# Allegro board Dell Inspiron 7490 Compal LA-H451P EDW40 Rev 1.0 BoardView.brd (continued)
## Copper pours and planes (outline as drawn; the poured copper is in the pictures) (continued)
+TBT_VBUS_L_PD on TOP (solid shape): 27.89,33.92 28.14,33.92 28.3,34.08 30.26,34.08 30.85,33.49 31.36,33.49 31.58,33.26 31.58,30.18 31.48,30.07 30.35,30.07 30.35,30.26 28.62,30.26 28.62,30.24 28.01,30.24 28.01,30.07 27.34,30.07 26.93,29.67 26.93,27.11 26.74,26.92 24.76,26.92 24.65,27.03 24.65,28.46 24.65,28.46 24.65,33.79 24.94,34.08 27.73,34.08
+TBT_VBUS_L_PD on BOTTOM (solid shape): 27.09,34 27.09,33.07 26.99,32.96 25.64,32.96 25.63,32.98 24.45,32.98 24.39,33.03 24.39,33.62 24.43,33.66 25.45,33.66 25.91,34.12 26.98,34.12
+TBT_VBUS_L_PD on BOTTOM (solid shape): 26.53,28.8 26.53,27.36 26.3,27.13 24.69,27.13 24.66,27.14 24.57,27.14 24.47,27.23 24.47,27.27 24.4,27.34 24.4,29.6 24.42,29.62 25.7,29.62
+TBT_VBUS_L_PD on IN1 (solid shape): 27.11,34.04 27.11,32.13 26.33,31.35 26.33,31.11 26.32,31.04 26.33,30.97 26.33,30.78 26.35,30.76 26.35,28.12 26.2,27.97 24.7,27.97 24.56,28.1 24.56,28.89 24.57,28.9 24.57,31.65 24.58,31.66 24.58,33.19 25.05,33.67 25.54,33.67 25.99,34.12 27.03,34.12
+TBTA_VBUS on TOP (solid shape): 33.29,34.99 33.29,34.45 33.38,34.36 33.61,34.36 33.67,34.3 33.67,33.47 34.44,32.69 34.44,30.36 34.2,30.11 32.19,30.11 32.04,30.26 32.04,34.43 32.04,34.43 32.04,34.99 32.12,35.07 33.22,35.07
+TBTA_VBUS on TOP (solid shape): outline of 249 points within 7.16,56.62 15.3,71.87
+TBTA_VBUS on BOTTOM (solid shape): 11.05,65.05 11.05,64.75 10.83,64.53 10.02,64.53 9.98,64.56 9.94,64.6 9.88,64.64 9.83,64.68 8.86,64.68 8.63,64.46 7.3,64.46 7.26,64.5 7.26,64.72 7.32,64.78 8.2,64.78 8.52,64.7 8.73,64.96 8.73,64.97 8.82,65.06 10.49,65.06 10.59,65.16 10.94,65.16
+TBTA_VBUS on BOTTOM (solid shape): 11.33,67.55 11.33,67.25 11.27,67.2 11.14,67.2 11.02,67.15 9.75,67.15 9.69,67.22 8.41,67.22 8.15,66.96 7.34,66.96 7.26,67.04 7.26,67.27 7.29,67.29 8.06,67.29 8.29,67.52 8.32,67.5 8.48,67.46 8.63,67.53 9.72,67.53 9.76,67.58 9.78,67.58 9.89,67.61 9.99,67.67 11.21,67.67
+TBTA_VBUS on IN2 (solid shape): outline of 430 points within 7.17,62.2 13.12,70.46
+TBTA_VBUS on IN3 (solid shape): outline of 367 points within 7.17,64.26 12.08,70.55
+TBTA_VBUS on VCC: 32.77,29.43 32.55,29.65 24.06,29.65 24.06,29.67 23.93,29.8 23.93,29.86 23.91,29.88 23.91,44.23 22.86,45.28 17.52,45.28 17.16,45.64 17.16,61.06 16.08,62.14 7.91,62.14 7.83,62.23 7.83,70.31 22.73,70.31 23.03,70.02 23.03,70.02 23.08,69.96 23.08,51.1 24.73,49.45 30.58,49.45 31.62,48.41 31.62,47.14 31.62,47.14 31.62,46.93 31.62,46.93 31.62,35 32.26,34.36 33.67,34.36 33.68,34.35 34.88,34.35 35.72,33.51 35.72,32.04 33.11,29.43
+TP_VDD on TOP (solid shape): 121.31,10.52 121.31,9.94 121.28,9.94 121.28,9.41 121.15,9.28 121,9.28 121,8.47 121.02,8.47 121.02,6.98 121,6.98 121,6.17 121.02,6.17 121.02,6.03 121.07,5.98 121.07,5.31 121.01,5.25 119.05,5.25 118.77,5.53 115.9,5.53 115.76,5.66 115.76,6.53 115.83,6.6 116.73,6.6 116.82,6.57 116.91,6.56 117.09,6.56 117.39,6.67 117.56,6.94 117.56,6.96 117.71,7.1 118.4,7.1 118.56,6.94 119.3,6.94 119.63,6.61 120.14,6.61 120.33,6.81 120.33,7.34 120.16,7.5 120.16,8.3 119.53,8.3 119.53,8.24 115.97,8.24 115.86,8.35 115.86,9.14 115.92,9.19 116.47,9.19 116.55,9.11 117.39,9.11 117.65,8.85 119.62,8.85 119.72,8.95 119.94,8.95 120.12,9.13 120.15,9.16 120.18,9.19 120.33,9.34 120.33,10.41 120.46,10.54 121.28,10.54
+TP_VDD on BOTTOM (solid shape): 125.86,12.79 125.86,10.94 125.64,10.73 123.86,10.73 123.78,10.81 123.78,12.9 123.81,12.93 125.72,12.93
+TP_VDD_N on TOP (solid shape): 117.4,9.87 117.47,9.87 117.68,9.65 118.35,9.65 118.39,9.62 118.39,9.2 118.33,9.14 117.62,9.14 117.49,9.27 116.57,9.27 116.49,9.35 116.49,9.84 116.58,9.93 117.34,9.93
+TP_VDD_P on TOP (solid shape): 121.28,11.61 121.28,10.94 121.21,10.88 120.47,10.88 120.05,10.46 119.45,10.46 119.39,10.52 119.39,11.08 119.47,11.16 119.95,11.16 120.47,11.69 121.2,11.69
+TS_VDD on TOP (solid shape): 41.45,54.87 41.81,54.87 41.88,54.8 41.88,54.09 41.7,53.91 41.31,53.91 41.31,51.73 40.3,51.73 39.67,52.36 39.67,52.76 40.78,53.87 40.78,54.87 41.44,54.87
+V_DDR_REF_CA on BOTTOM (solid shape): 176.38,60.6 176.38,59.55 176.37,59.55 176.37,58.68 176.28,58.59 176.27,58.59 176.13,58.51 176.05,58.37 176.05,58.36 176.02,58.33 175.48,58.33 175.47,58.38 175.42,58.51 175.3,58.6 175.27,58.61 175.27,59.44 175.21,59.5 175.21,60.68 175.25,60.72 176.27,60.72
+V_DDR_REFA_R on BOTTOM (solid shape): 179.28,61.55 179.28,59.88 177.94,58.54 177.94,58.51 177.93,58.5 177.86,58.31 177.94,58.12 177.94,57.97 177.9,57.95 177.71,57.73 177.83,57.46 177.87,57.38 177.85,57.3 177.76,57.22 177.3,57.22 177.2,57.32 177.2,57.59 177.38,57.77 177.38,58.13 177.33,58.18 177.33,58.38 177.38,58.43 177.38,58.61 177.74,58.97 177.74,60.16 178.24,60.65 178.24,61.55 178.3,61.61 179.22,61.61
+V_DDR_REFB_R on BOTTOM (solid shape): 177.57,61.59 177.57,60.09 177.25,59.77 177.25,58.49 177.2,58.43 177.2,58.13 177.25,58.08 177.25,57.83 177.13,57.7 176.77,57.7 176.64,57.83 176.64,61.08 176.54,61.18 176.54,61.58 176.59,61.64 177.53,61.64
+VCHGR on TOP: 94.75,12.94 95.63,12.94 95.81,12.76 95.81,11.18 95.69,11.06 91.99,11.06 91.67,11.37 91.67,13.25 92.22,13.8 93.9,13.8 94.75,12.95
+VDISPLAY_VCC on TOP (solid shape): 16.1,48.48 16.25,48.48 16.74,47.98 16.74,46.75 16.62,46.63 13.9,46.63 13.49,47.04 12.57,47.04 12.46,47.16 12.46,48.41 13.21,49.16 15.42,49.16
+VDISPLAY_VCC on IN2 (solid shape): outline of 570 points within 13.16,36.24 30.16,49.26
+VREFCA on BOTTOM (solid shape): 179.72,78.6 179.72,78.04 179.39,77.71 178.78,77.71 178.7,77.79 178.7,78.74 179.58,78.74
+VREFCA on BOTTOM (solid shape): 187.77,78.42 187.77,77.83 187.79,77.82 187.79,77.18 187.71,77.1 186.29,77.1 186.21,77.17 186.21,78.36 186.48,78.63 187.57,78.63
+VREFCA on IN1 (solid shape): 162.91,78.86 163.08,78.8 163.25,78.86 164.66,78.86 164.83,78.8 165.01,78.86 167.83,78.86 168.55,78.13 171.38,78.13 172.11,78.86 187.78,78.86 188,78.64 188,77.19 187.83,77.02 187.3,77.02 186.07,78.25 184.6,78.25 183.95,77.6 175.71,77.6 174.97,76.86 173,76.86 172.3,77.56 167.48,77.56 167.16,77.89 166.78,77.89 166.71,77.89 166.65,77.89 146.04,77.89 146.04,77.88 145.56,77.4 142.06,77.4 141.79,77.66 141.79,78.2 142.35,78.76 155.14,78.76 155.24,78.86
+VREFCA on IN3 (solid shape): 143.52,78.53 143.52,78.05 143.51,78.04 143.51,76.7 143.41,76.59 142.66,76.59 142.55,76.71 142.55,78.08 142.55,78.64 142.64,78.72 143.33,78.72
+VREFDQ_A on BOTTOM (solid shape): 183.04,63.93 183.04,63.53 182.85,63.34 182.3,63.34 182.23,63.28 182.16,63.28 182.16,63.2 182.13,63.18 182.13,61.4 184.7,58.83 184.7,55.15 184.72,55.13 184.72,54.07 184.61,53.96 183.9,53.96 183.71,54.15 183.71,55.03 184.11,55.44 184.11,58.43 181.59,60.95 181.59,60.95 181.41,61.14 181.41,61.57 181.19,61.79 180.6,61.79 180.57,61.76 178.28,61.76 178.24,61.8 178.24,62.18 178.36,62.3 180.25,62.3 180.46,62.51 180.46,63.23 180.6,63.36 181.47,63.36 182.16,64.06 182.91,64.06
+VREFDQ_B on BOTTOM (solid shape): 151.22,64.33 151.83,64.33 151.89,64.27 151.89,63.36 151.83,63.3 150.6,63.3 150.37,63.54 150.37,64.52 150.53,64.68 150.87,64.68
+VREFDQ_B on BOTTOM (solid shape): 162.08,64.36 162.08,62.61 161.95,62.47 161.1,62.47 161.02,62.55 161.02,63.72 160.95,63.79 160.95,64.53 161.07,64.66 161.79,64.66
+VREFDQ_B on BOTTOM (solid shape): 180.27,63.27 180.27,62.79 180.22,62.74 179.68,62.74 179.65,62.77 177.5,62.77 177,62.27 177,62.21 176.99,62.19 176.99,61.76 176.54,61.76 176.52,61.79 176.52,63.18 176.79,63.45 180.09,63.45
ADJ_UM2 on TOP (solid shape): 29.89,36.37 29.89,36.17 29.73,36.01 28.74,36.01 28.55,35.82 28.55,35.49 28.44,35.38 27.57,35.38 27.49,35.46 27.49,36.13 27.53,36.17 27.92,36.17 28.05,36.3 28.05,36.4 28.07,36.42 29.84,36.42
ADP_CHG on BOTTOM (solid shape): 195.03,21.26 195.03,21.25 193.62,19.85 193.62,17.53 193.45,17.36 192.96,17.36 192.96,17.39 191.99,17.39 191.99,18 192.11,18.12 192.49,18.12 192.62,18.25 192.65,18.25 192.65,18.28 193.13,18.76 193.13,19.85 193.25,19.97 193.25,20.15 194.53,21.43 194.53,21.94 194.78,22.19 195.03,22.19
ALL_SYS_PWRGD on TOP (solid shape): 64.69,18.04 64.69,17.17 64.62,17.1 63,17.1 62.78,17.32 62.78,17.81 63.06,18.09 63.57,18.09 63.83,18.03 64.08,18.12 64.6,18.12
B+ on TOP (solid shape): 74.24,13.22 74.24,11.61 73.95,11.32 72.75,11.32 72.65,11.42 70.53,11.42 70.3,11.65 70.3,13.17 70.49,13.36 74.11,13.36
B+ on TOP (solid shape): 68.92,61.56 68.92,60.24 68.69,60.01 67.68,60.01 67.25,60.44 61.33,60.44 60.54,59.64 58.09,59.64 57.91,59.82 57.91,60.2 59.73,62.01 68.47,62.01
B+ on TOP (solid shape): 140.23,16.45 140.23,16.03 141.76,14.51 141.76,13.17 141.69,13.11 138.52,13.11 138.39,13.24 138.39,13.55 138.58,13.74 138.58,14.12 138.39,14.31 137.31,14.31 135.92,15.71 135.92,16.66 136.04,16.79 139.89,16.79
B+ on TOP (solid shape): 44.52,72.95 47.41,72.95 48.18,73.72 49.07,73.72 49.18,73.62 49.18,70.12 48.95,69.89 45.22,69.89 44.98,69.65 44.98,68 45.1,67.88 45.1,65.24 45.05,65.18 44.62,65.18 44.48,65.32 44.48,66.35 44.16,66.66 44.16,66.67 44.11,66.73 44.04,66.78 44.04,66.79 43.73,67.1 43.73,67.74 43.04,68.43 43.04,69.78 43.15,69.89 43.15,72.45 42.21,73.38 41.32,73.38 41.26,73.44 41.26,74.12 41.34,74.2 41.35,74.2 41.44,74.29 43.19,74.29
B+ on TOP (solid shape): 200.82,59.2 200.82,59.09 200.76,59.09 200.76,58.25 200.82,58.25 200.82,57.48 200.72,57.38 200.09,57.38 200.05,57.35 199.91,57.35 199.76,57.2 199.76,56.11 199.98,55.89 200.01,55.84 200.19,55.66 201.29,55.66 201.38,55.57 201.38,54.45 201.05,54.11 200.88,54.11 200.57,53.81 199.13,53.81 199.01,53.94 199.01,54.36 198.98,54.38 198.98,57.75 199.01,57.76 199.23,58.07 199.01,58.38 198.98,58.4 198.98,58.49 199.1,58.61 199.73,58.61 199.91,58.79 199.91,59.2 199.94,59.24 200.78,59.24
B+ on BOTTOM (solid shape): 188.38,7.56 188.38,6.49 188.09,6.21 186.75,6.21 186.47,6.48 185.89,6.48 185.62,6.21 185.62,5.7 185.52,5.6 180.8,5.6 180.8,5.6 180.51,5.6 180.43,5.68 180.43,7.33 180.81,7.71 188.23,7.71
B+ on BOTTOM (solid shape): 9.9,22.36 9.9,16.9 9.36,16.37 9.36,13.98 9.16,13.78 8.15,13.78 8.15,13.79 8.09,13.79 7.98,13.9 7.98,17.13 8.35,17.5 8.35,20.83 8.07,21.11 8.06,21.11 7.98,21.2 7.98,22.46 8.15,22.63 9.63,22.63
B+ on BOTTOM (solid shape): 137.4,19.26 138,19.26 138,19.26 138.15,19.1 138.15,18.69 138.22,18.62 138.22,17.1 138.54,16.77 138.55,16.77 138.61,16.71 138.68,16.71 138.68,16.66 139.75,16.66 139.75,16.71 139.85,16.71 139.85,16.66 140.04,16.66 140.04,16.66 140.04,16.23 139.93,16.12 135.51,16.12 135.11,16.52 135.11,18.39 135.03,18.47 134.56,18.47 134.51,18.53 134.51,19.15 134.62,19.26 137.4,19.26
B+ on BOTTOM (solid shape): 141.67,14.34 141.67,13.84 141.69,13.82 141.69,12.39 141.87,12.21 145.1,12.21 145.28,12.03 145.28,7.73 144.43,6.88 141.53,6.88 139.86,8.55 137.67,8.55 137.46,8.77 137.46,9.89 136.71,10.64 136.71,13.83 137.68,13.83 137.68,13.78 137.69,13.73 137.7,13.68 137.73,13.63 137.76,13.59 137.8,13.55 137.84,13.52 137.88,13.5 137.93,13.48 137.98,13.48 138.04,13.48 138.09,13.48 138.14,13.5 138.18,13.52 138.23,13.55 138.26,13.59 138.29,13.63 138.32,13.68 138.33,13.73 138.34,13.78 138.34,13.83 138.33,13.88 138.32,13.93 138.29,13.98 138.26,14.02 138.23,14.06 138.18,14.09 138.14,14.11 138.09,14.13 138.04,14.14 137.98,14.14 137.93,14.13 137.88,14.11 137.84,14.09 137.8,14.06 137.76,14.02 137.73,13.98 137.7,13.93 137.69,13.88 137.68,13.83 136.71,13.83 136.71,14.07 137.06,14.42 138.75,14.42 141.58,14.42
B+ on BOTTOM (solid shape): 207.55,31.53 207.55,30.79 207.96,30.38 208.14,29.7 208.14,29.12 208.11,29.1 206.39,29.1 206.29,29.2 206.29,29.95 206.22,30.02 205.46,30.02 205.37,29.94 205.35,29.94 205.25,29.83 205.25,29.82 205.21,29.77 205.21,27.26 205.45,27.02 205.45,23.79 205.45,23.79 205.45,23.33 204.81,22.7 204.81,18.12 204.62,17.93 204.01,17.93 203.67,17.59 203.67,17.29 203.37,16.98 202.41,16.98 202.4,17 200.73,17 200.62,17.11 200.62,17.97 200.62,19.01 200.78,19.17 202.47,19.17 202.47,18.19 202.65,18.01 203.78,18.01 203.98,18.2 203.98,19.13 203.77,19.34 202.64,19.34 202.47,19.17 200.78,19.17 200.88,19.27 201.26,19.27 201.51,19.52 201.51,20.54 202.27,21.3 202.27,22.57 203.35,23.64 203.35,25.75 203.22,25.87 202.76,25.87 202.48,26.15 202.48,27.24 202.83,27.6 202.83,29.38 202.73,29.48 202.12,29.48 202.02,29.38 202.02,28.97 201.94,28.89 201.43,28.89 201.36,28.97 201.36,30.75 201.42,30.81 202.8,30.81 202.81,30.83 202.98,30.83 203.16,31 203.16,31.51 203.42,31.77 207.31,31.77
B+ on BOTTOM (solid shape): outline of 834 points within 35.89,11.78 90.01,72.91
B+ on IN1 (solid shape): 60.83,60.35 60.83,59.72 60.66,59.54 57.92,59.54 57.8,59.67 57.8,60.34 57.95,60.49 60.69,60.49
B+ on IN3 (solid shape): 188.39,7.53 188.39,5.83 188.04,5.49 181.06,5.49 180.87,5.68 180.87,7.72 180.96,7.81 188.1,7.81
B+ on IN3 (solid shape): 10.08,22.49 10.08,14.97 9.22,14.12 8.56,14.12 8.37,14.3 8.37,17.13 8.36,17.14 8.36,22.73 8.43,22.8 9.77,22.8
B+ on IN3 (solid shape): 205.32,27.19 205.32,23.59 204.64,22.9 201.46,22.9 200.83,23.54 200.83,24.68 201.21,25.06 202.43,25.06 202.93,25.57 202.93,27.55 203.09,27.7 204.81,27.7
B+ on TOP: 99.43,12.25 98.39,13.3 97.98,13.3 97.67,13.5 97.37,13.3 94.77,13.3 94.21,13.86 94.04,13.86 94.02,13.88 93.76,13.88 93.43,14.21 93.43,14.45 90.7,14.45 89.7,13.46 89.2,13.46 88.82,13.83 88.82,14.18 89.49,14.85 89.49,16.76 89.68,16.95 96.37,16.95 96.39,16.92 97.13,16.92 97.23,16.82 97.23,15.88 97.24,15.88 97.24,15.64 97.39,15.49 103.61,15.49 103.63,15.5 103.74,15.6 103.74,15.61 103.77,15.64 103.77,16.85 103.95,17.03 106.84,17.03 106.88,17.03 106.98,17.03 107.09,16.92 107.09,13.43 106.9,13.24 104.38,13.24 103.97,12.83 100.97,12.83 100.94,12.81 100.9,12.81 100.7,12.61 100.7,12.56 100.39,12.25
B+ on VCC: 44.63,56.22 42.89,57.95 42.89,80.53 43.14,80.78 46.15,80.78 46.66,79.85 47.65,79.48 49.45,79.48 49.81,79.53 50.16,79.66 50.69,80.12 50.95,80.78 60.16,80.78 60.16,61.11 60.86,60.42 61.1,60.42 61.54,59.97 61.54,56.62 61.14,56.22
B+ on VCC: 9.34,1.02 9.09,1.27 9.09,2.25 9.03,2.49 8.85,2.68 8.85,12.72 8.73,12.85 8.73,16.02 8.38,16.37 8.38,17.08 8.9,17.61 8.9,20.77 8.27,21.4 8.27,23.02 8.82,23.56 9.14,23.56 9.29,23.41 9.4,23.41 17.51,23.41 19.15,21.77 19.15,15.13 20.88,13.39 86.93,13.39 88.34,14.8 98.39,14.8 99.79,13.41 136.43,13.41 137.28,14.25 141.96,14.25 142.81,13.41 184.46,13.41 187.91,16.86 190.24,16.86 192.19,14.92 195.21,14.92 197.27,16.98 197.27,20.1 197.29,20.12 197.29,20.33 197.27,20.34 197.27,58.53 198.16,59.42 201.78,59.42 203.74,52.12 200.63,48.99 203.75,45.88 205.41,45.88 210.61,26.47 212.3,21.62 214.69,17.09 214.69,9.8 212.13,7 214.69,4.2 214.69,3.02 198.53,3.02 198.53,3.02 49.97,3.02 49.52,4.08 48.45,4.52 46.65,4.52 45.58,4.08 45.13,3.02 30.97,3.02 30.9,3.46 30.7,3.86 30.15,4.34 29.45,4.52 27.65,4.52 26.58,4.08 26.13,3.02 18.6,3.02 16.86,2.47 15.76,1.02
B+ on IN2: 57.24,60.03 57.24,60.61 57.32,60.82 57.24,61.03 57.24,67.84 56.24,68.85 47.59,68.85 46.56,69.88 46.44,69.88 46.36,69.88 46.28,69.88 45.18,69.88 45.04,70.02 45.04,73.18 45.23,73.37 45.26,73.37 47.83,73.92 49.16,76.19 49.16,76.24 50.47,76.24 50.56,76.18 50.54,76.07 50.77,75.56 51,76.07 50.98,76.18 51.07,76.24 58.24,76.24 58.25,76.2 58.57,75.97 58.89,76.2 58.9,76.24 59.83,76.24 60.1,75.97 60.1,61.18 59.91,60.99 59.91,60.67 60.1,60.48 60.73,60.48 60.99,60.23 60.99,59.84 60.92,59.78 58.85,59.78 58.62,59.55 57.72,59.55
B+_1.2V on TOP (solid shape): 202.02,57 202.02,56.9 202.07,56.86 202.07,56.8 202.08,56.78 202.08,56.46 202.17,56.38 202.17,56.2 202.25,56.12 202.25,56.11 202.25,55.36 202.13,55.25 201.69,55.25 201.56,55.38 201.56,55.57 201.27,55.86 200.64,55.86 200.48,56.02 200.03,56.02 199.89,56.16 199.89,57.14 199.96,57.22 201.8,57.22
B+_1.2V on BOTTOM (solid shape): 192.07,68.33 193.97,68.33 194.11,68.2 194.11,68.04 193.98,67.92 191.72,67.92 191.01,67.21 190.01,67.21 189.91,67.31 189.91,68.65 189.91,68.65 189.91,68.91 190.23,69.23 191.18,69.23
B+_1.2V on IN1 (solid shape): 201.47,57 201.55,57 201.71,56.93 201.89,56.95 202.05,56.95 202.12,56.87 202.12,55.85 202.1,55.83 200.38,55.83 200.24,55.97 200.24,57.29 200.32,57.37 201.1,57.37
B+_1.2V on IN3 (solid shape): 195.06,66.05 198.41,62.7 198.4,62.67 198.39,62.46 198.49,62.27 198.85,61.92 199.2,61.92 200.4,60.71 200.43,60.63 200.39,60.55 200.24,60.23 200.48,59.96 200.48,57.76 201.28,56.96 201.28,56.32 201.13,56.18 200.62,56.18 200.6,56.19 199.58,57.2 199.58,57.22 199.5,57.29 199.5,58.82 199.43,58.89 199.43,60.08 192.17,67.34 191.35,67.34 191,67.69 191,68.12 191.23,68.36 192.75,68.36
B+_1.05V on BOTTOM (solid shape): 129.52,26.15 129.52,24.76 129.25,24.5 129.25,24.36 129.27,24.34 129.27,23.79 128.7,23.23 128.7,22.05 128.5,21.85 128.37,21.85 128.16,22.05 128.16,22.44 128.17,22.44 128.17,23.39 128.18,23.41 128.18,24 128.18,24 128.24,24 128.46,24.23 128.46,24.28 128.59,24.41 128.59,26.15 128.66,26.22 129.45,26.22
B+_1.05V on BOTTOM (solid shape): 128.68,20.33 128.68,18.81 128.99,18.49 128.99,17.76 129.13,17.62 129.73,17.62 129.84,17.52 129.84,16.09 130.09,15.84 131.41,15.84 131.58,16.02 131.58,17.15 132.26,17.82 132.26,18.98 132.28,19 133.15,19 133.87,18.28 134.79,18.28 134.87,18.2 134.87,16.63 134.65,16.41 134.56,16.41 134.17,16.46 134.01,16.11 134,16.1 134,14.34 133.87,14.21 129.12,14.21 128.79,14.54 128.79,15.63 128.32,15.63 128.17,15.78 128.17,16.22 128.16,16.22 128.16,19.84 128.16,19.84 128.16,20.19 128.16,20.2 128.16,20.36 128.28,20.47 128.53,20.47
B+_1.05V on TOP: 128.14,23.83 128.14,17.08 128.43,16.79 131.58,16.79 131.83,16.54 131.83,15.94 131.99,15.78 132.8,15.78 132.99,15.97 132.99,17.57 132.81,17.75 130,17.75 129.34,18.42 129.34,21.97 128.94,22.37 128.94,24.02 128.83,24.13 128.43,24.13
B+_1.8V on TOP (solid shape): 71.07,21.13 71.07,20.67 71.55,20.19 71.55,14.76 71.7,14.61 71.97,14.61 72.01,14.57 72.01,13.87 71.96,13.82 70.55,13.82 70.39,13.99 70.39,18.3 70.26,18.43 70.26,19.6 70.68,20.02 70.68,21.15 70.75,21.22 70.98,21.22
B+_3V on BOTTOM (solid shape): 10.53,16.36 10.53,15.01 10.92,14.62 11.7,14.62 11.79,14.53 12.95,14.53 13.08,14.66 14.06,14.66 14.16,14.56 14.16,13.59 13.52,12.95 13.52,12.05 13.46,11.99 13.07,11.99 12.99,12.06 12.99,12.24 12.93,12.3 12.16,12.3 12.08,12.22 12.08,11.46 11.95,11.33 9.65,11.33 9.57,11.42 9.57,16.3 9.68,16.42 10.48,16.42
B+_5V on BOTTOM (solid shape): 13.44,29.07 13.44,28.25 13.07,27.88 12.03,27.88 11.53,27.38 11.53,25.84 11.22,25.54 9.26,25.54 9.08,25.36 9.08,24.25 9.27,24.07 14.21,24.07 14.29,23.99 14.29,23.61 14.16,23.49 12.18,23.49 11.19,22.5 11.19,21.24 11.11,21.17 10.31,21.17 10.24,21.24 10.24,22.71 10.14,22.82 7.57,22.82 7.26,23.13 7.26,27.84 7.46,28.03 8.68,28.03 8.68,28.04 11.47,28.04 11.61,28.18 11.61,29.04 11.72,29.15 13.36,29.15
B+_+1.35VGPU on TOP (solid shape): 71.44,60.97 71.44,54.63 71.31,54.49 69.19,54.49 69.13,54.55 69.13,56.1 69.57,56.54 69.57,58.44 69.29,58.73 69.29,61.44 69.48,61.64 70.78,61.64
BA on TOP (solid shape): 103.64,6.9 103.64,5.67 103.37,5.39 102.96,5.39 102.82,5.26 101.67,5.26 101.61,5.31 101.61,6.25 101.51,6.35 101.23,6.35 101.04,6.54 100.84,6.54 100.78,6.6 100.78,7.26 100.83,7.31 103.24,7.31
BA_PWR on BOTTOM (solid shape): 200.27,29.18 200.27,28.94 200.29,28.92 200.29,28 200.12,27.83 199.57,27.83 199.47,27.93 199.47,28.4 199.47,28.41 199.47,29.19 199.67,29.39 200.05,29.39
BGATE_CHG on TOP (solid shape): 95.79,10.78 95.79,8.94 95.74,8.9 95.12,8.9 95.05,8.96 95.05,10.15 94.8,10.41 94.67,10.41 94.6,10.47 94.6,10.81 94.69,10.9 95.67,10.9
BGATE_CHG on IN3 (solid shape): 198.4,26.48 200.76,26.48 201.33,25.91 201.33,25.41 201.23,25.31 198.41,25.31 198.24,25.47 197.69,25.47 197.57,25.6 197.57,26.37 197.68,26.49 198.4,26.49
BOOT1_CHG on BOTTOM (solid shape): 196.65,22.16 196.65,21.22 197.32,20.55 198.55,20.55 198.62,20.48 198.62,19.67 198.56,19.61 197.68,19.61 197.65,19.65 197.65,19.79 197.15,20.29 197.06,20.38 197.06,20.38 196.38,21.06 196.38,22.16 196.42,22.2 196.61,22.2
BOOT2_CHG on BOTTOM (solid shape): 200.08,23.94 200.08,23.35 200.16,23.27 200.37,23.27 200.42,23.22 200.42,22.52 200.41,22.51 199.9,22.51 199.79,22.62 199.79,23 199.56,23.23 199.56,23.83 199.43,23.95 198.01,23.95 197.95,24.01 197.95,24.16 197.99,24.2 199.82,24.2
BST_1.2V on BOTTOM (solid shape): 196.01,68.16 196.01,67.02 196.27,66.75 197.33,66.75 197.4,66.67 197.4,66.03 197.33,65.96 196.33,65.96 195.41,66.88 195.41,67.68 195.2,67.89 194.67,67.89 194.61,67.96 194.61,68.22 194.7,68.32 195.85,68.32
BST_1.2V_R on BOTTOM (solid shape): 197.3,68.98 197.3,67.12 197.25,67.07 196.35,67.07 196.26,67.16 196.26,68.93 196.4,69.08 197.2,69.08
BST_1.05V on BOTTOM (solid shape): 127.6,24.4 127.6,24.33 127.92,24 127.99,24 128.04,23.96 128.04,22.49 127.94,22.4 127.71,22.4 127.62,22.49 127.62,22.71 126.29,24.03 126.29,24.55 126.35,24.6 127.39,24.6
BST_1.05V_R on BOTTOM (solid shape): 128.37,25.98 128.37,25.45 128.27,25.34 127.87,25.34 127.86,25.35 127.58,25.35 127.47,25.23 126.46,25.23 126.34,25.36 126.34,26.02 126.47,26.15 128.2,26.15
BST_1.8V on TOP (solid shape): 71.05,22.4 71.05,21.65 70.91,21.51 70.85,21.51 70.69,21.67 70.69,22.01 70.18,22.53 70.18,22.53 68.34,22.53 68.27,22.46 68.27,21.96 68.09,21.79 67.27,21.79 67.1,21.96 67.1,22.81 67.3,23.01 70.44,23.01
BST_1.8V_R on TOP (solid shape): 68.44,25.11 68.44,23.77 68.43,23.76 68.43,23.4 68.25,23.21 67.3,23.21 67.23,23.29 67.23,23.85 67.38,24 67.38,25.08 67.5,25.21 68.35,25.21
BST_3V on BOTTOM (solid shape): 14.63,14.52 14.63,13.21 14.35,12.93 14.35,12.41 14.27,12.33 13.7,12.33 13.67,12.36 13.67,12.91 14.3,13.54 14.3,14.63 14.33,14.65 14.49,14.65
BST_3V_R on BOTTOM: 13.79,11.22 13.65,11.36 13.65,11.93 13.78,12.07 16.24,12.07 16.29,12.01 16.29,11.26 16.26,11.22
BST_5V on BOTTOM (solid shape): 16.42,23.82 16.42,21.06 16.32,20.96 15.39,20.96 15.28,21.07 15.28,21.68 15.46,21.85 15.46,21.88 15.46,21.88 15.46,23.17 15.46,23.23 15.46,23.62 15.31,23.77 14.92,23.77 14.84,23.84 14.84,23.99 14.89,24.04 16.2,24.04
BST_5V_R on BOTTOM (solid shape): 16.34,20.31 16.34,19.76 15.92,19.34 15.92,18.77 15.86,18.71 15.28,18.71 15.22,18.77 15.22,20.17 15.27,20.23 15.31,20.3 15.31,20.31 15.35,20.35 15.35,20.39 16.25,20.39
BST_+1.35VGPU on TOP (solid shape): 71.46,54.12 71.46,53.35 71.36,53.25 70.75,53.25 69.99,54.02 69.2,54.02 69.13,54.09 69.13,54.27 69.2,54.35 71.23,54.35
BST_+1.35VGPU_R on TOP (solid shape): 72.94,54.17 72.94,52.35 72.84,52.25 72.23,52.25 71.95,52.53 71.95,54.17 72.03,54.25 72.86,54.25
BST_GPU1 on BOTTOM (solid shape): 57.54,75.45 57.54,74.7 56.92,74.07 56.92,73.49 56.83,73.4 56.1,73.4 56.07,73.42 56.07,74.23 56.35,74.51 56.53,74.51 56.73,74.71 56.73,75.45 56.8,75.53 57.46,75.53
BST_GPU2 on BOTTOM (solid shape): 57.51,67.95 57.51,67.43 56.91,66.83 56.91,65.79 56.89,65.78 56.2,65.78 56.12,65.85 56.12,66.92 56.58,67.37 56.58,67.4 56.63,67.45 56.63,67.99 56.73,68.09 57.37,68.09
BST_GT on BOTTOM (solid shape): 200.47,37.1 200.47,36.39 199.94,35.85 199.94,34.45 199.84,34.35 199.29,34.35 199.17,34.47 199.17,35.11 199.49,35.43 199.49,36.99 199.64,37.14 200.43,37.14
BST_IA1 on BOTTOM (solid shape): 166.54,15.49 166.54,14.98 166.68,14.84 168.13,14.84 168.37,14.6 168.37,13.78 168.35,13.75 167.42,13.75 167.31,13.86 167.31,14.26 167.11,14.47 165.93,14.47 165.87,14.53 165.87,14.94 165.87,14.94 165.87,15.49 165.91,15.54 166.49,15.54
BST_IA2 on BOTTOM: 176.17,14.61 176.17,13.8 176.14,13.77 175.25,13.77 175.17,13.85 175.17,14.13 174.89,14.4 174.51,14.4 174.04,14.86 173.95,14.86 173.95,14.87 173.73,14.87 173.61,14.99 173.61,15.45 173.69,15.53 174.3,15.53 174.3,15.53 174.36,15.53 174.42,15.46 174.42,14.99 174.42,14.94 174.45,14.91 175.21,14.91 175.43,14.69 176.09,14.69
BST_IA3 on BOTTOM: 183.86,14.48 183.86,13.78 183.84,13.76 183.01,13.76 182.98,13.79 182.98,14.35 182.84,14.49 182.11,14.49 181.69,14.9 181.22,14.9 181.16,14.96 181.16,15.44 181.29,15.56 181.91,15.56 181.98,15.5 181.98,15.09 181.98,15.08 181.98,15 182.11,14.87 183.47,14.87
BST_SA on BOTTOM (solid shape): 141.51,21.47 142.25,21.47 142.35,21.36 142.35,20.65 142.33,20.63 141.47,20.63 141.16,20.94 140.41,20.94 140.38,20.97 140.38,21.55 140.41,21.59 141.4,21.59
CSIN_CHG on BOTTOM (solid shape): 195.84,22.16 195.84,20.98 196.12,20.7 196.54,20.7 196.98,20.25 196.98,19.77 196.89,19.67 196.39,19.67 196.24,19.53 196.24,19.19 196.21,19.16 195.5,19.16 195.43,19.23 195.43,20.6 195.57,20.75 195.57,22.17 195.62,22.21 195.78,22.21
CSIP_CHG on BOTTOM (solid shape): 195.44,22.17 195.44,20.8 195.3,20.66 195.3,19.18 195.25,19.13 193.82,19.13 193.76,19.18 193.76,19.8 193.81,19.85 194.43,19.85 194.64,20.06 194.64,20.61 195.15,21.12 195.15,21.2 195.16,21.21 195.16,22.2 195.17,22.21 195.41,22.21
DCIN_CHG on BOTTOM (solid shape): 194.63,22.53 194.63,22.42 194.4,22.19 194.4,21.58 193.12,20.31 193.12,20.02 192.85,19.75 192.85,19.33 192.53,19.01 191.22,19.01 190.97,18.76 190.08,18.76 189.95,18.89 189.95,20.16 190.08,20.28 190.84,20.28 191.02,20.11 191.02,20.02 191.14,19.9 192.37,19.9 192.42,19.96 192.79,19.96 192.79,20.64 193.76,21.62 193.76,22.54 193.82,22.6 194.56,22.6
DGPU_MAIN_EN# on TOP (solid shape): 119.66,55.58 119.66,55.15 119.62,55.12 119.07,55.12 118.99,55.03 118.99,54.59 118.89,54.49 118.42,54.49 118.3,54.61 118.3,55.63 118.37,55.69 119.55,55.69
DGPU_PWR_EN#_R on TOP (solid shape): 120.15,48.25 120.15,47.28 120.04,47.16 119.55,47.16 119.36,47.35 118.83,47.35 118.78,47.39 118.78,47.79 118.88,47.9 119.21,47.9 119.66,48.34 120.06,48.34
EN_0.6V on BOTTOM (solid shape): 192.7,67.51 192.7,66.73 192.5,66.53 190.67,66.53 190.38,66.23 190.38,65.56 190.12,65.31 190.12,64.65 190.04,64.58 189.46,64.58 189.37,64.67 189.37,65.2 189.67,65.51 189.67,66.83 189.83,66.99 191.63,66.99 192.19,67.54 192.68,67.54
EN_1.2V on BOTTOM (solid shape): 193.19,67.47 193.19,66.51 191.79,65.1 191.79,64.66 191.71,64.58 191.59,64.58 191.43,64.41 191.43,63.97 191.3,63.85 190.71,63.85 190.62,63.94 190.62,64.41 190.69,64.49 190.83,64.49 191.02,64.68 191.02,65.12 191.19,65.29 191.28,65.29 191.52,65.54 191.52,66.08 191.67,66.22 192.47,66.22 192.88,66.63 192.88,67.48 192.94,67.54 193.13,67.54
EN_R on TOP (solid shape): 51.24,7.94 51.24,7.36 51.37,7.23 52.19,7.23 52.29,7.23 52.38,7.13 52.38,6.62 52.31,6.54 49.82,6.54 49.49,6.21 48.52,6.21 48.33,6.4 48.33,6.97 48.58,7.22 49.59,7.22 49.79,7.42 49.79,7.92 49.87,7.99 51.18,7.99
FB_1.2V on BOTTOM (solid shape): 194.18,67.47 194.18,65.76 194.57,65.37 195.2,65.37 195.3,65.27 195.3,64.74 195.2,64.64 193.14,64.64 193.08,64.7 193.08,65.32 193.89,66.13 193.89,67.48 193.93,67.53 194.13,67.53
GPU_B+ on TOP (solid shape): 53.13,73.88 53.13,72.46 52.75,72.08 51.5,72.08 51.43,72.01 51.43,70.18 51.73,69.88 53.63,69.88 53.79,69.72 53.79,60.81 53.08,60.1 49.37,60.1 49.14,60.33 49.14,60.34 49.09,60.4 49.09,69.81 49.84,70.56 49.84,73.46 50.48,74.1 52.91,74.1
GPU_B+ on BOTTOM (solid shape): 53.03,73.27 56.76,73.27 56.76,73.26 57.27,73.26 57.34,73.33 57.94,73.33 57.98,73.29 57.98,72.82 57.93,72.77 57.25,72.77 57.16,72.86 55.04,72.86 54.64,72.45 53.12,72.45 52.74,72.07 51.55,72.07 51.33,72.29 51.33,73.64 51.63,73.93 52.37,73.93
GPU_B+ on BOTTOM (solid shape): 52.9,65.65 56.76,65.65 56.95,65.65 57.25,65.65 57.36,65.76 57.97,65.76 58.01,65.72 58.01,65.21 57.96,65.15 57.12,65.15 56.98,65.29 55.07,65.29 54.66,64.88 53.16,64.88 52.93,64.65 51.5,64.65 51.19,64.96 51.19,65.66 51.2,65.67 51.2,65.86 51.34,66.01 52.54,66.01
IA_B+ on TOP (solid shape): 183.43,11.61 183.43,8.02 183.2,7.79 180.99,7.79 180.03,8.75 163.32,8.75 163.03,9.04 163.03,10.28 162.65,10.66 162.65,11.36 162.65,12.19 163.03,12.58 182.46,12.58
IA_B+ on BOTTOM (solid shape): outline of 109 points within 166.03,5.52 186.27,15.66
INV_PWR_SRC on TOP (solid shape): 38.7,76.75 39.25,76.2 40.04,76.2 40.15,76.08 40.15,75.71 40.4,75.45 41.99,75.45 42.1,75.34 42.1,74.48 42.06,74.45 40.22,74.45 39.72,74.94 38.86,74.94 38.71,74.79 37.79,74.79 37.64,74.94 37.64,76.29 37.68,76.29 37.68,76.34 37.84,76.5 37.84,76.65 37.95,76.76 38.7,76.76
INV_PWR_SRC_C on TOP (solid shape): 40.17,74.31 40.53,74.31 40.68,74.16 40.68,73.52 40.58,73.41 40.07,73.41 39.44,74.04 39.06,74.04 39.03,74.06 39.03,74.6 39.1,74.67 39.82,74.67
LCDVDD_EN on TOP (solid shape): 45.7,54.02 45.7,53.82 45.78,53.75 45.9,53.75 45.9,53.75 46.33,53.75 46.36,53.71 46.36,53.32 46.33,53.3 44.9,53.3 44.85,53.35 44.85,54.2 44.9,54.25 45.47,54.25
LDO_+1.35VGPU on TOP (solid shape): 65.82,53.87 66.88,53.87 67.02,54.01 67.62,54.01 67.75,53.88 67.75,53.11 67.7,53.06 67.03,53.06 66.77,53.33 65.1,53.33 64.82,53.61 64.82,54.07 64.9,54.14 65.55,54.14
LG1_CHG on BOTTOM (solid shape): 190.72,6.57 190.72,5.68 190.59,5.55 189.83,5.55 189.7,5.68 189.7,6.57 189.83,6.69 190.59,6.69
LG1_CHG on IN3 (solid shape): 198.18,22 198.18,20.33 197.97,20.11 197.23,20.11 197.14,20.21 197.14,20.53 197.41,20.8 197.41,22.02 197.49,22.09 198.09,22.09
LG1_CHG on IN3 (solid shape): 190.64,6.6 191.01,6.6 191.11,6.5 191.11,5.87 190.97,5.74 190.64,5.74 190.62,5.76 190.07,5.76 189.93,5.91 189.93,6.46 190.07,6.61 190.63,6.61
LG2_CHG on BOTTOM (solid shape): 209.35,19.3 209.55,19.3 209.64,19.2 209.64,18.19 209.48,18.03 209.43,18.03 209.4,18 208.9,18 208.27,18.63 208.27,19.21 208.36,19.3 209.35,19.3
LG2_CHG on IN3 (solid shape): 209.59,19.08 209.59,17.98 209.41,17.81 208.15,17.81 208.01,17.95 208.01,19.13 208.12,19.25 209.42,19.25
LX1_CHG on BOTTOM (solid shape): 197.43,22.17 197.43,21.3 197.63,21.1 198.88,21.1 199.53,20.45 199.53,19.38 199.48,19.33 198.92,19.33 198.79,19.46 198.79,20.51 198.53,20.76 198.15,20.76 197.52,20.76 197.16,21.12 197.16,22.14 197.2,22.18 197.42,22.18
LX1_CHG on BOTTOM (solid shape): 200.46,17.79 200.46,15.22 201.16,14.52 201.16,9.23 200.27,8.35 196.43,8.35 195,6.92 190.14,6.92 190.06,6.99 190.06,9.46 190.36,9.75 195.16,9.75 195.18,9.73 195.62,10.18 195.62,14.72 195.63,14.73 195.63,15.04 196.01,15.42 198.68,15.42 198.68,15.42 199.08,15.42 199.28,15.61 199.28,17.74 199.36,17.82 200.43,17.82
LX1_CHG on IN3 (solid shape): 199.49,19.58 199.49,18.71 199.43,18.65 198.7,18.65 198.63,18.72 198.63,19.83 198.65,19.86 199.21,19.86
LX1_CHG on IN3 (solid shape): 201.33,14.85 201.33,14.18 201,13.86 199.82,13.86 199.6,14.08 199.6,14.8 199.86,15.07 201.1,15.07
LX2_CHG on BOTTOM (solid shape): 199.61,23 199.61,22.57 199.84,22.34 200.5,22.34 200.55,22.29 200.55,21.36 200.52,21.33 199.86,21.33 199.26,21.94 199.26,23.02 199.13,23.14 199.11,23.15 198.04,23.15 197.98,23.2 197.98,23.33 198.05,23.39 199.21,23.39
LX2_CHG on BOTTOM (solid shape): 208.11,22.7 208.11,19.6 208.11,18.63 208.14,18.61 208.14,18.58 208.85,17.87 208.88,17.87 209.64,17.11 209.64,7.58 209.38,7.33 205.07,7.33 204.56,7.84 204.56,14.14 206.21,15.79 206.21,17.72 205.93,18 205.39,18 205.19,18.19 205.19,22.7 205.32,22.82 207.99,22.82
LX2_CHG on IN3 (solid shape): 201.68,22.19 201.68,21.61 201.56,21.49 200.56,21.49 200.27,21.77 200.27,22.27 200.34,22.33 201.54,22.33
LX2_CHG on IN3 (solid shape): 207.17,22.21 207.17,20.47 207.07,20.37 206.3,20.37 206.11,20.55 206.11,22.17 206.32,22.38 207,22.38
LX_1.2V on TOP (solid shape): 198.8,70.88 198.8,69.05 198.83,68.97 198.83,68.63 198.92,68.53 198.92,66.29 198.65,66.02 194.23,66.02 194.02,66.24 194.02,68.82 194.2,69.01 196.72,69.01 197.14,69.43 197.14,70.79 197.22,70.87 197.22,70.89 197.25,70.92 198.76,70.92
LX_1.2V on BOTTOM (solid shape): 197.66,70.62 197.66,69.37 197.62,69.33 196.34,69.33 196.25,69.24 196.25,69.24 196.12,69.11 196.12,68.64 195.98,68.5 195.72,68.5 195.71,68.49 193.51,68.49 193.44,68.56 193.44,68.67 193.55,68.77 194.3,68.77 194.91,69.38 195.36,69.38 195.57,69.59 195.57,70.14 195.85,70.42 196.76,70.42 197.05,70.7 197.57,70.7
LX_1.2V on IN1 (solid shape): 198.84,68.92 198.84,67.1 198.63,66.88 196.11,66.88 195.75,67.24 195.75,68.79 196.23,69.27 198.5,69.27
LX_1.2V on IN3 (solid shape): 197.66,70.7 197.66,69.29 198.08,68.87 198.08,66.89 197.95,66.77 195.8,66.77 195.65,66.91 195.65,70.2 195.79,70.35 196.83,70.35 196.95,70.46 196.95,70.59 197.15,70.79 197.57,70.79
LX_1.05V on TOP (solid shape): 134.84,23.01 134.84,21.93 134.25,21.35 132.83,21.35 132.63,21.55 132.63,23.6 132.74,23.71 134.14,23.71
LX_1.05V on BOTTOM (solid shape): 134.24,24.73 134.24,23.55 134.84,22.95 134.84,21.51 133.22,19.9 133.22,19.39 133.15,19.32 131.36,19.32 131.25,19.43 131.25,20.36 131,20.61 128.23,20.61 128.09,20.75 128.09,21.52 128.23,21.65 130.96,21.65 131.66,22.36 131.66,24.63 131.86,24.83 134.14,24.83
LX_1.8V on TOP (solid shape): 70.14,29.08 70.14,27.78 70.13,27.77 70.13,27.57 71.16,26.54 71.56,26.54 71.87,26.24 71.87,22.31 71.53,21.97 71.53,20.83 71.45,20.75 71.29,20.75 71.24,20.81 71.24,22.47 70.56,23.15 69.31,23.15 69.03,23.44 69.03,25.05 68.63,25.45 67.43,25.45 67.35,25.53 67.35,28.05 67.8,28.5 67.8,28.84 68.09,29.12 70.1,29.12
LX_3V on TOP (solid shape): 18.64,14.9 18.64,12.05 18.31,11.72 16.88,11.72 16.52,12.08 16.52,14.87 16.75,15.1 18.44,15.1
LX_3V on BOTTOM (solid shape): 19.22,16.47 19.22,13.16 18.71,12.66 18.71,11.65 18.45,11.38 16.71,11.38 16.62,11.47 16.62,12.37 16.36,12.64 16.36,14.1 15.81,14.65 14.78,14.65 14.64,14.79 12.94,14.79 12.83,14.68 12.04,14.68 12.03,14.7 12.03,14.96 12.04,14.97 12.92,14.97 13,15.05 14.17,15.05 14.54,15.41 16.38,15.41 16.6,15.63 16.6,16.62 16.7,16.72 18.97,16.72
LX_5V on TOP (solid shape): 19.54,21.68 19.54,19.32 19.54,19.32 19.54,19.14 19.32,18.92 17.39,18.92 17.08,19.23 17.08,21.71 17.21,21.84 19.39,21.84
LX_5V on BOTTOM (solid shape): 17.7,25.38 18.92,25.38 19.3,25 19.3,18.91 19.06,18.67 16.27,18.67 16.19,18.75 16.19,19.34 16.32,19.47 16.6,19.47 16.82,19.7 16.82,23.71 16.31,24.22 13.67,24.22 13.6,24.29 13.6,24.45 13.72,24.57 14.87,24.57 15.86,25.55 17.53,25.55
LX_+1.35VGPU on TOP (solid shape): 69.07,57 69.07,56.35 69.07,56.34 69.07,56.22 69,56.15 69,54.5 69,54.5 69,54.02 69.2,53.83 69.85,53.83 71.65,52.03 72.81,52.03 73.07,51.77 73.07,50.04 72.18,49.15 67.9,49.15 67.71,49.34 67.71,51.68 68.31,52.28 68.31,53.91 68.77,54.38 68.77,56.97 68.87,57.08 69,57.08
LX_+1.35VGPU on BOTTOM (solid shape): 71.34,55.83 71.34,53.97 71.18,53.82 70.22,53.82 70.11,53.92 70.11,55.85 70.24,55.98 71.19,55.98
LX_+1.35VGPU on IN3 (solid shape): 70.84,53.92 70.84,52.69 70.7,52.55 70.45,52.55 70.05,52.95 70.05,54 70.13,54.08 70.68,54.08
LX_GPU1 on TOP (solid shape): 57.94,77.82 57.94,77.03 58.01,76.96 58.58,76.96 58.93,76.61 58.93,76.09 58.76,75.92 57.94,75.92 57.77,75.76 55.37,75.76 55.24,75.89 55.24,77.9 55.55,78.21 57.54,78.21
LX_GPU1 on BOTTOM (solid shape): 61.46,76.96 61.46,71.03 61.18,70.75 55.25,70.75 55.11,70.89 55.11,72.57 55.25,72.71 56.92,72.71 57.15,72.48 58.24,72.48 58.67,72.91 58.67,74.91 57.84,75.74 56.93,75.74 56.81,75.87 56.81,76.4 56.8,76.41 56.8,76.44 56.72,76.52 55.46,76.52 55.38,76.6 55.38,76.88 55.48,76.97 61.44,76.97
LX_GPU2 on TOP (solid shape): 60.09,66.17 60.09,64.57 58.75,63.23 57.98,63.23 57.62,63.59 57.62,66.26 57.79,66.43 59.84,66.43
LX_GPU2 on BOTTOM (solid shape): 58.11,69.15 61.38,69.15 61.68,68.85 61.68,63.67 61.67,63.65 61.67,61.75 61.56,61.64 58.2,61.64 57.94,61.9 57.94,62.59 57.52,63.01 55.87,63.01 55.86,63.01 55.4,63.01 55.16,63.25 55.16,65.08 55.22,65.14 56.83,65.14 57,64.98 58.07,64.98 58.23,65.14 58.23,68.06 57.98,68.32 56.8,68.32 56.72,68.39 56.72,69.09 56.8,69.17 58.09,69.17
LX_GT on BOTTOM (solid shape): 197.74,44.91 197.74,41.87 197.97,41.63 198.7,41.63 199.17,41.16 199.17,40.25 199.48,39.94 201.21,39.94 201.46,39.69 201.46,37.98 201.36,37.88 198.92,37.88 198.69,37.65 198.06,37.65 197.69,37.28 197.69,35.22 197.8,35.12 198.92,35.12 199.02,35.01 199.02,34.44 198.84,34.26 195.46,34.26 194.6,35.12 194.6,44.9 195.03,45.33 197.33,45.33
LX_IA1 on TOP (solid shape): 172.24,17.79 172.24,16.06 171.89,15.71 168.28,15.71 168.11,15.88 168.11,18.15 168.36,18.41 171.62,18.41
LX_IA1 on BOTTOM (solid shape): 172.13,18.56 172.13,15.79 171,14.66 171,12.89 170.93,12.82 169.14,12.82 169.06,12.9 169.06,14.59 169.16,14.69 169.16,15.71 169.1,15.77 166,15.77 165.9,15.86 165.9,18.43 166.38,18.91 171.78,18.91
LX_IA2 on TOP (solid shape): 177.63,17.62 177.63,15.71 177.51,15.58 174.59,15.58 174.33,15.84 174.33,17.36 174.71,17.74 177.51,17.74
LX_IA2 on BOTTOM (solid shape): 178.99,18.81 178.99,15.12 178.81,14.94 178.81,12.98 178.67,12.84 176.92,12.84 176.8,12.95 176.8,14.47 176.99,14.65 176.99,15.76 176.92,15.83 173.57,15.83 173.52,15.89 173.52,18.04 174.4,18.93 178.87,18.93
LX_IA3 on TOP (solid shape): 184.94,20.99 184.94,19.42 184.56,19.04 181.47,19.04 181.31,19.2 181.31,19.65 181.43,19.77 182.9,19.77 183.14,20 183.14,21.03 183.3,21.19 184.74,21.19
LX_IA3 on BOTTOM (solid shape): 187.05,19.04 187.05,15.51 186.53,14.99 186.53,13.01 186.38,12.86 184.68,12.86 184.52,13.03 184.52,14.49 184.74,14.71 184.74,15.68 184.62,15.81 181.29,15.81 181.23,15.86 181.23,16.39 181.36,16.52 181.96,16.52 182.18,16.74 182.18,17.8 181.44,18.55 181.44,19.52 181.54,19.62 182.18,19.62 182.18,19.63 186.46,19.63
LX_SA on TOP (solid shape): 144.2,24.69 144.2,22.73 144.07,22.6 141.9,22.6 141.82,22.68 141.82,24.72 141.88,24.79 144.1,24.79
LX_SA on BOTTOM (solid shape): 143.95,26.1 143.95,23.92 144.97,22.9 144.97,19.79 144.91,19.73 143.17,19.73 143.09,19.81 143.09,22.21 142.45,22.85 141.06,22.85 140.83,22.62 140.24,22.62 140.08,22.46 140.08,20.93 140.04,20.9 139.47,20.9 139.38,20.99 139.38,23.09 139.82,23.53 140.25,23.53 140.47,23.76 140.75,23.76 141.19,24.2 141.19,26.1 141.4,26.3 143.74,26.3
MODE_1.2V on BOTTOM (solid shape): 193.68,67.47 193.68,66.15 192.95,65.42 192.95,64.75 192.92,64.72 192.39,64.72 192.35,64.76 192.35,65.32 193.4,66.37 193.4,67.48 193.45,67.53 193.62,67.53
PD_L_DRAIN1 on TOP (solid shape): 24.29,31.25 24.29,28.96 24.17,28.85 22.48,28.85 22.36,28.96 22.36,31.34 22.49,31.47 24.06,31.47
PD_L_DRAIN1 on BOTTOM (solid shape): 25.46,31.46 25.46,31.36 25.43,31.32 24.52,31.32 24.46,31.32 24.4,31.29 24.39,31.28 24.37,31.28 24.27,31.18 24.27,27.78 24.12,27.62 23.94,27.62 23.84,27.73 23.84,27.77 23.85,27.8 23.85,28.59 23.84,28.69 23.71,28.82 22.67,28.82 22.59,28.74 22.59,28.64 22.59,28.59 22.59,27.8 22.59,27.75 22.59,27.65 22.54,27.6 22.31,27.6 22.26,27.65 22.26,31.51 22.31,31.56 25.36,31.56
PD_L_DRAIN1 on IN1 (solid shape): 24.36,31.31 24.36,29.11 24.14,28.89 22.57,28.89 22.35,29.1 22.35,31.32 22.57,31.53 24.14,31.53
PD_L_DRAIN1 on IN2 (solid shape): 24.33,31.35 24.33,29.25 23.93,28.86 22.45,28.86 22.29,29.02 22.29,31.38 22.44,31.53 24.14,31.53
PD_L_DRAIN1 on IN3: 22.36,31.36 22.36,29.12 22.64,28.84 24.04,28.84 24.24,29.05 24.24,31.43 24.09,31.59 22.59,31.59
PD_L_DRAIN2 on TOP (solid shape): 24.32,34.28 24.32,31.93 24.17,31.78 22.45,31.78 22.27,31.97 22.27,34.17 22.48,34.38 24.22,34.38
PD_L_DRAIN2 on BOTTOM (solid shape): 24.22,35.68 24.22,32.25 24.45,32.02 25.34,32.02 25.44,31.92 25.44,31.76 25.39,31.71 25.34,31.72 25.31,31.72 24.52,31.72 24.49,31.72 24.46,31.71 22.34,31.71 22.27,31.78 22.27,35.64 22.33,35.7 22.5,35.7 22.59,35.6 22.59,35.59 22.59,34.8 22.59,34.75 22.59,34.63 22.64,34.58 22.74,34.58 22.82,34.57 22.89,34.58 23.14,34.58 23.22,34.57 23.29,34.58 23.54,34.58 23.62,34.57 23.69,34.58 23.75,34.58 23.87,34.71 23.87,35.61 23.98,35.72 24.18,35.72
PD_L_DRAIN2 on IN1 (solid shape): 24.29,34.33 24.29,31.93 24.16,31.8 22.53,31.8 22.4,31.94 22.4,34.29 22.54,34.43 24.18,34.43
PD_L_DRAIN2 on IN2 (solid shape): 24.27,34.2 24.27,32.03 24.05,31.8 22.39,31.8 22.22,31.98 22.22,34.21 22.36,34.35 24.12,34.35
PD_L_DRAIN2 on IN3: 22.29,34.53 22.29,31.82 22.36,31.74 24.22,31.74 24.27,31.79 24.27,34.48 24.07,34.69 22.44,34.69
PLT_RST_VGA#_QV147 on BOTTOM (solid shape): 114.98,75.78 114.98,75.26 114.85,75.12 114.85,74.64 114.72,74.51 113.35,74.51 113.17,74.69 113.17,75.1 113.32,75.25 113.5,75.25 113.6,75.35 113.6,75.41 113.61,75.41 113.61,75.81 113.63,75.83 114.92,75.83
PSI_GPU on TOP (solid shape): 37.59,64.76 37.59,64.13 37.92,63.79 39.01,63.79 39.06,63.73 39.06,63.6 38.98,63.52 37.4,63.52 37.31,63.43 36.37,63.43 36.34,63.46 36.34,64.04 36.18,64.2 35.3,64.2 35.27,64.23 35.27,64.77 35.92,64.77 35.92,64.8 37.55,64.8
PWM_CORE1 on BOTTOM (solid shape): 168.34,11.52 168.34,10.46 168.19,10.31 167.17,10.31 167.1,10.38 167.1,11.56 167.16,11.61 168.25,11.61
SIO_SLP_S3 on TOP (solid shape): 62.01,18.66 62.01,17.9 61.66,17.54 59.14,17.54 58.99,17.69 58.99,18.41 59.19,18.61 61.05,18.61 61.19,18.75 61.92,18.75
SN_1.2V on TOP (solid shape): 198,73.04 198.8,73.04 198.8,73.04 199.02,73.04 199.03,73.03 199.03,72.44 198.79,72.2 198.79,71.3 198.77,71.27 197.4,71.27 197.33,71.34 197.33,72.78 197.66,73.11 197.93,73.11
SN_1.05V on TOP (solid shape): 136.56,23.7 136.56,21.08 136.44,20.96 135.65,20.96 135.6,21.01 135.6,21.64 135.29,21.95 135.29,23.67 135.34,23.73 136.54,23.73
SN_1.8V on TOP (solid shape): 71.88,29.01 71.88,28.43 71.96,28.35 73,28.35 73.04,28.31 73.04,27.64 72.94,27.54 70.92,27.54 70.77,27.69 70.77,28.97 70.92,29.11 71.78,29.11
SN_3V on TOP (solid shape): 20.64,15.74 20.64,13.17 20.49,13.02 19.47,13.02 19.24,13.25 19.24,15.69 19.44,15.89 20.49,15.89
SN_5V on TOP (solid shape): 18.64,24.31 18.64,23.27 18.71,23.2 19.18,23.2 19.25,23.13 19.25,22.14 19.23,22.12 17.6,22.12 17.47,22.24 17.47,24.3 17.58,24.41 18.54,24.41
SN_+1.35VGPU on BOTTOM (solid shape): 74.74,56.68 74.74,55.46 73.95,54.68 73.95,54.27 73.88,54.19 72.89,54.19 72.81,54.27 72.81,55.82 72.96,55.97 73.06,55.97 73.08,55.98 73.56,55.98 73.77,56.2 73.77,56.63 73.95,56.81 74.61,56.81
SN_GPU1 on TOP (solid shape): 60.49,77.45 60.49,76.73 60.6,76.63 61.27,76.63 61.34,76.55 61.34,75.85 61.22,75.73 59.22,75.73 59.09,75.86 59.09,77.45 59.25,77.61 60.33,77.61
SN_GPU2 on TOP (solid shape): 62.26,65.81 62.26,65.08 62.37,64.97 63.1,64.97 63.2,64.87 63.2,63.87 63.1,63.77 61.01,63.77 60.84,63.94 60.84,65.76 61.01,65.93 62.14,65.93
SN_GT on BOTTOM (solid shape): 197.52,47.27 197.52,45.93 197.38,45.79 194.71,45.79 194.56,45.93 194.56,47.27 194.68,47.39 197.4,47.39
SN_IA1 on TOP (solid shape): 170.9,20.03 170.9,19.52 170.27,18.89 168.11,18.89 167.98,19.01 167.98,20.03 168.11,20.16 170.78,20.16
SN_IA2 on TOP (solid shape): 177.25,19.65 177.25,19.27 177.38,19.14 178.02,19.14 178.14,19.01 178.14,18.38 178.02,18.25 174.46,18.25 174.33,18.38 174.33,19.78 174.59,20.03 176.87,20.03
SN_IA3 on TOP (solid shape): 187.18,22.02 187.18,18.98 187.05,18.85 186.16,18.85 185.78,19.23 185.78,20.88 186.04,21.13 186.29,21.13 186.42,21.26 186.42,22.02 186.55,22.15 187.05,22.15
SNUB1_CHG on BOTTOM (solid shape): 197.93,17.63 197.93,16.16 197.83,16.06 196.02,16.06 195.86,16.21 195.86,17.42 196.26,17.82 197.74,17.82
SNUB2_CHG on BOTTOM (solid shape): 206.01,17.74 206.01,16.22 205.91,16.12 204.91,16.12 204.71,16.32 204.71,16.83 204.58,16.96 203.92,16.96 203.85,17.03 203.85,17.59 204.07,17.81 204.68,17.81 204.73,17.86 205.89,17.86
TMDS_CFG0 on IN3: 20.2,41.29 20.06,41.43 20.06,42.39 20.14,42.47 20.44,42.47 20.51,42.39 20.51,42.07 20.62,41.96 20.63,41.95 20.81,41.71 21.11,41.72 21.19,41.72 21.24,41.67 21.24,41.4 21.12,41.29
UG1_CHG on BOTTOM (solid shape): 189.45,6.95 189.45,5.68 189.32,5.55 188.73,5.55 188.54,5.74 188.54,7.01 188.6,7.08 189.32,7.08
UG1_CHG on IN3 (solid shape): 189.42,7.79 189.42,6.15 189.21,5.94 188.67,5.94 188.55,6.06 188.55,7.8 188.66,7.9 189.31,7.9
UG1_CHG on IN3 (solid shape): 197.23,22.02 197.23,21.12 196.57,20.46 195.9,20.46 195.67,20.69 195.67,21.05 196.81,22.18 197.07,22.18
UG2_CHG on BOTTOM (solid shape): 203.85,19.08 203.85,18.25 203.73,18.13 202.7,18.13 202.59,18.24 202.59,19.11 202.69,19.21 203.72,19.21
UG2_CHG on IN3 (solid shape): 200.18,24.17 200.18,23.56 200.06,23.43 198.36,23.43 198.19,23.61 198.19,24.17 198.32,24.3 200.05,24.3
UG2_CHG on IN3 (solid shape): 204.45,19.67 204.45,19.23 204.45,19.23 204.45,18.24 204.24,18.04 203.03,18.04 202.84,18.22 202.84,19.78 203.04,19.98 204.13,19.98
VGA_CORE_EN# on TOP (solid shape): 114.42,75.6 114.69,75.6 114.86,75.43 114.86,74.43 114.7,74.28 113.66,74.28 113.56,74.38 113.56,75.3 113.39,75.46 113.39,75.85 113.43,75.89 114.14,75.89
WWAN_GPIO_PERST#_R on TOP (solid shape): 56.35,46.75 56.35,46.32 56.25,46.22 55.08,46.22 54.98,46.12 54.32,46.12 54.29,46.14 54.29,46.78 54.34,46.83 56.27,46.83
N2712313 on BOTTOM (solid shape): 52.62,75.44 52.62,74.82 53.19,74.24 53.39,74.24 53.39,74.24 53.89,74.24 53.9,74.21 53.91,74.2 53.91,73.45 53.88,73.42 53.15,73.42 52.54,74.03 52.54,74.06 51.91,74.68 51.91,75.42 51.98,75.49 52.57,75.49
N2726340 on BOTTOM (solid shape): 52.53,67.99 52.53,67.28 53.04,66.77 53.07,66.74 53.85,66.74 53.91,66.68 53.91,65.83 53.86,65.78 53.02,65.78 52.64,66.16 52.64,66.33 52.19,66.78 51.9,66.78 51.76,66.93 51.76,67.87 51.9,68.02 52.5,68.02
N20727249 on TOP (solid shape): 117.3,73.54 117.3,72.43 117.18,72.32 115.17,72.32 114.98,72.5 114.98,73.54 115.21,73.77 117.07,73.77
N31764615 on BOTTOM (solid shape): 153.91,29.07 153.91,27.53 153.87,27.49 153.32,27.49 153.24,27.58 153.24,29.12 153.26,29.14 153.84,29.14
N33308105 on TOP (solid shape): 106,8.6 106,7.67 105.77,7.44 103.61,7.44 103.28,7.78 103.28,7.78 103.11,7.94 103.11,9.24 103.27,9.39 105.21,9.39
N33308158 on BOTTOM (solid shape): 189.45,20.05 189.45,18.4 189.58,18.28 191.1,18.28 191.21,18.17 191.21,17.23 191.08,17.1 188.66,17.1 188.3,17.47 188.3,20.22 188.36,20.28 189.22,20.28
N33308361 on BOTTOM (solid shape): 199.72,18.85 199.72,18.3 199.62,18.2 198.77,18.2 198.74,18.17 197.7,18.17 197.65,18.22 197.65,18.92 197.74,19.01 199.56,19.01
N33308373 on BOTTOM (solid shape): 202.14,23.08 202.14,21.64 201.82,21.32 200.83,21.32 200.69,21.46 200.69,23.18 200.79,23.29 201.93,23.29
N33310985 on BOTTOM (solid shape): 14.01,20.77 14.01,20.23 14.11,20.13 14.11,19.57 14.06,19.52 13.02,19.52 12.92,19.62 12.92,19.94 12.97,19.99 13.2,19.99 13.3,20.09 13.3,20.77 13.37,20.84 13.93,20.84
N36804565 on TOP (solid shape): 46.62,6.54 47.27,6.54 47.45,6.36 47.45,5.73 47.29,5.57 46.72,5.57 46.02,6.27 45.67,6.27 45.57,6.36 45.57,6.86 46.3,6.86
N45032542 on TOP (solid shape): 116.19,54.88 116.19,54.47 116.32,54.35 117.03,54.35 117.16,54.22 117.16,53.58 117.03,53.46 115.4,53.46 115.13,53.74 115.13,54.85 115.25,54.98 116.09,54.98

Small or netless copper shapes (teardrops, artwork), in the pictures only: 94 on TOP, 91 on BOTTOM, 140 on IN1, 341 on IN3

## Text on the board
Ref Des/Silkscreen Bottom: EDP | KB/BL | KB | FP | Battery | Touch Pad | IO2 | RTC | S4 | H19 | H4 | S6 | H18 | S3 | H16 | H11 | S2 | S5 | S1 | UL indicator
User.Comments: LA-H451P | 2020-06-21 | 2019-06-21 | EDW40 | Win
Ref Des/Silkscreen Top: IO1 | H19 | H4 | H18 | H16 | S7 | H42 | A | LA-H451P | HF
GND4: GND4
XSECTION_CHART: LAYER | NO. | L1 | L2 | L3 | L4 | L5 | L6 | L7 | L8 | L9 | L10 | LA-H451P | GND2 | GND3 | GND1 | GND4 | IN1 | VCC | IN2 | IN3 | BOT | TOP | * | L1: TOP | L2: GND1 | L3: IN1 | L4: GND2 | L5: VCC | L6: IN2 | L7: GND3 | L8: IN3 | L9: GND4 | L10: BOTTOM | DESIGN CROSS SECTION CHART | ___________________________ | TOTAL THICKNESS 34.05 MIL | 1-10 | 1-2 | 1-3 | 2-3 | 3-8 | 8-10 | 8-9 | 9-10
BODY_CENTER: 168.6 | 166.6 | 11.3 | 9.8 | 33.6 | -5 | -3 | 55 | 81.8 | 157.6 | 88.6 | 0 | X:6.9 | Y:44.24 | 17.8 | 16.3 | 6 | 165.6 | Print white paint on TOP silkscreen | Print white paint on BOT silkscreen | 2 | 147.3 | 145.8 | X:212.81 | Y:119.07 | 163.6 | 75 | 108.6 | 130 | 153.8 | 152.3 | 3.8 | 3.5 | 5 | 8.5 | 11.71 | 10 | 13.71 | 19.71 | 32 | 39.71 | 62 | 94.71 | 109.86 | 125 | 144.71 | 157.71 | 180 | 187.71 | 200 | 206 | 208 | 209.71 | 211.21 | 214.71 | 216.21 | 215.91 | 217.71 | 219.71 | R5X4 | Barcode area:8X8 on top side only X2 | Tooling Hole:2.7mm(+/-1.5mil) x4 | Tooling Hole:2mm x3 | LA-H451P | REV:0.3(TOP) | 0.127mm | 173.6
User.42: FIGURE | SIZE | 8.0 | 22.0 | 102.0 | 110.0 | 130.0 | 134.0 | 142.0 | 146.0 | 24.0 | 31.0 | 35.0 | 43.0 | 63.0 | 71.0 | 31.0x28.0 | 63.0x24.0 | 63.0x35.0 | 75.0x24.0 | 161.0x142.0 | 79.0x63.0 | 91.0x20.0 | DRILL CHART: TOP to BOTTOM | ALL UNITS ARE IN MILS | TOLERANCE | +3.0/-3.0 | +2.0/-2.0 | PLATED | NON-PLATED | QTY | 2596 | 19 | 3 | 1 | 4 | 2
User.43: FIGURE | SIZE | 8.0 | DRILL CHART: IN1 to IN3 | ALL UNITS ARE IN MILS | TOLERANCE | +3.0/-3.0 | PLATED | QTY | 2576
User.44: FIGURE | SIZE | 4.0 | DRILL CHART: IN3 to BOTTOM | ALL UNITS ARE IN MILS | TOLERANCE | +1.0/-1.0 | PLATED | QTY | 3479
User.45: BOTTOM | LAYER | NAME | GND3 | GND4 | IN3 | GND1 | GND2 | TOP | IN1 | VCC | IN2 | 0.86mm_2+6+2(1086-1080-1080 1oz)(50ohm)(Top G-V In1 G-V In2 G-V G-V In3 G-V BOT).pdf | STACKUP: 10 LAYER | trace Width | 40 ohm | 3.7 | 5 | 50 ohm | 3.2 | 2.6 | 2.5 | 70 ohm | THICKNESS=0.86mm | 4.3/3.7 | Width/Space | 80 ohm | 3.5/4.5 | 3.6/4.4 | 3.1/4.8 | 85 ohm | 90 ohm | 3.2/4.8 | 100 ohm | 2.4/5.6 | 2.6/5.4 | L5/L7 | L7/L9 | L2/L4 | L9 | REF | L2 | FIGURE | SIZE | 4.0 | DRILL CHART: IN3 to GND4 | ALL UNITS ARE IN MILS | DRILL CHART: TOP to GND1 | DRILL CHART: TOP to IN1 | DRILL CHART: GND1 to IN1 | DRILL CHART: GND4 to BOTTOM | TOLERANCE | +1.0/-1.0 | PLATED | QTY | 2569 | 2096 | 261 | 2662
